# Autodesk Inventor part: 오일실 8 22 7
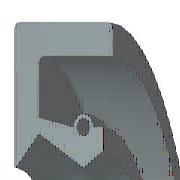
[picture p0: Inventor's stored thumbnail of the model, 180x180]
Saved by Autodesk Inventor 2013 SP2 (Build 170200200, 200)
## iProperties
IsCustomPart: 1
Created: 2012-02
Part Number: 오일실 8 22 7
Material: 고무
Description: 오일-실
Document SubType Name: Modeling
Standard: KS B 2804
Designer: mduedu
Standards Organization: KS
Language: ko-KR
Size Designation: D - 8 22 7
Categories: <MemberInstance><Categories><Category DisplayName="샤프트 부품" InternalName="7f7aeb1f-a693-4053-b835-cee3144e0d98" Mnemonic="SHFT"><Category DisplayName="실링" Intern
Density: 0.93 g/cm^3
Author: mduedu
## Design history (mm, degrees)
revolve "본체" stored, may be unused: angle "d17" = 90 deg
revolve "스프링1" stored, may be unused: angle "d18" = 90 deg
body "Solid1"
sketch "스케치1"
  geometry: L1 (0, 11)-(7, 11); L2 (7, 9.25)-(1.75, 9.25); L3 (1.75, 5.75)-(4.9, 4); L4 (4.9, 4)-(0, 4); L5 (0, 0)-(9.586, 0) reference; L6 (4.9, 4)-(6.3, 4.875); L7 (0, 18)-(0, -3) reference; L8 (-1.941, 0)-(11.507, 0) reference; L9 (4.2, 6.1)-(1.75, 6.59); L10 (1.75, 6.59)-(1.75, 9.25); L11 (0, 11)-(0, 4.088); L12 (4.9, 4)-(0, 4); L13 (1.75, 5.75)-(0.152, 4.028); L14 (7, 11)-(7, 9.25); L15 (5.6, 6.1)-(6.3, 6.1); L16 (6.3, 6.1)-(6.3, 4.875); C1 r 0.455 at (4.9, 6.1); A1 r 0.7 centre (4.9, 6.1) between (5.6, 6.1) and (4.2, 6.1); A2 r 0.088 centre (0.088, 4.088) between (0, 4.088) and (0.152, 4.028); 1 further point
  constraints: 28 end point, 5 horizontal alignment, 5 point on line, 4 point on circle, 4 vertical alignment, 3 centre point, 3 tangent, 2 collinear, 2 horizontal, 2 perpendicular, 1 coincident, 1 parallel
  dimensions: "d0" = 22 diameter of L1 L5 (= SD2); "d1" = 1.75 distance of L1.end L2.start (= SD); "d2" = 0.91 diameter of C1 (= SPDI); "d3" = 1.4 diameter of A1 (= SPDA); "d4" = 8 diameter of L3.end L5 (= NND); "d5" = 11.5 diameter of L3.start L5 (= TKDM); "d7" = 13.18 diameter of L9.end L5 (= TKDM + 0.24 x SWDT); "d8" = 1.75 distance between parallel lines of L11 L10 (= SD); "d9" = 4.9 distance from line of L11 C1.centre (= SPDST); "d10" = 12.2 diameter of C1.centre L5 (= HLDM); "d11" = 0.0875 radius of A2 (= 0.25 x LAB); "d12" = 6.3 distance between parallel lines of L11 L16 (= SDI); "d13" = 9.75 diameter of L6.end L5 (= ABDM); "d14" = 7 distance from line of L11 L1.end (= SWDT)
fillet "모깎기1" dims "d6" = 0.3 (= RR)
other parameters: "SD2" = 22 [user parameter; used in 1 equation term], "SWDT" = 7 [user parameter; used in 2 equation terms], "RR" = 0.3 [user parameter; used in 1 equation term], "SD" = 1.75 [user parameter; used in 2 equation terms], "NND" = 8 [user parameter; used in 1 equation term], "SPDA" = 1.4 [user parameter; used in 1 equation term], "SPDI" = 0.91 [user parameter; used in 1 equation term], "TKDM" = 11.5 [user parameter; used in 2 equation terms], "HLDM" = 12.2 [user parameter; used in 1 equation term], "ABDM" = 9.75 [user parameter; used in 1 equation term], "SDI" = 6.3 [user parameter; used in 1 equation term], "SPDST" = 4.9 [user parameter; used in 1 equation term], "LAB" = 0.35 [user parameter; used in 1 equation term], "d15" = 0, "d16" = 0, "d19" = 0
